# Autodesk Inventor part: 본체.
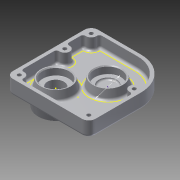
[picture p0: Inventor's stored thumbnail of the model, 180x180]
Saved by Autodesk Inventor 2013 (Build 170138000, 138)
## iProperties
Created: 2015-11
Part Number: 본체.
Material: 알루미늄 6061
Document SubType Name: Modeling
Designer: Administrator
Density: 1 g/cm^3
Author: Administrator
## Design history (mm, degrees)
sketch "스케치1"
  geometry: L1 (-44.906, -34.091)-(39.094, -34.091); L2 (47.094, -26.091)-(47.094, 28.909); L3 (7.094, 68.909)-(-44.906, 68.909); L4 (-52.906, 60.909)-(-52.906, -26.091); A1 r 40 centre (7.094, 28.909) between (47.094, 28.909) and (7.094, 68.909); A2 r 8 centre (-44.906, 60.909) between (-44.906, 68.909) and (-52.906, 60.909); A3 r 8 centre (-44.906, -26.091) between (-52.906, -26.091) and (-44.906, -34.091); A4 r 8 centre (39.094, -26.091) between (39.094, -34.091) and (47.094, -26.091); 4 further points
  constraints: 8 end point, 8 point on circle, 8 tangent, 6 point on line, 4 centre point, 2 equal radius, 2 parallel, 1 horizontal, 1 perpendicular
  dimensions: "d0" = 103 distance of point (-52.906, 68.909) point (-52.906, -34.091); "d2" = 100 distance of point (-52.906, -34.091) point (47.094, -34.091); "d3" = 40 radius of A1; "d4" = 8 radius of A2
extrude "돌출1" new body sketch "스케치1" distance "d5" = 18; taper "d6" = 0 deg
sketch "스케치2"
  geometry: L1 (47.094, -26.091)-(47.094, 28.909) reference; L2 (7.094, 68.909)-(-44.906, 68.909) reference; L3 (-52.906, 60.909)-(-52.906, -26.091) reference; L4 (-44.906, -34.091)-(39.094, -34.091) reference; A1 r 40 centre (7.094, 28.909) between (47.094, 28.909) and (7.094, 68.909) reference; A2 r 8 centre (-44.906, 60.909) between (-44.906, 68.909) and (-52.906, 60.909) reference; A3 r 8 centre (-44.906, -26.091) between (-52.906, -26.091) and (-44.906, -34.091) reference; A4 r 8 centre (39.094, -26.091) between (39.094, -34.091) and (47.094, -26.091) reference; 1 further point
feature "쉘1" dims "d9" = 4
sketch "스케치3"
  geometry: L1 (88, 4)-(88, 59) reference; L2 (52, 95)-(0, 95) reference; L3 (-4, 91)-(-4, 4) reference; L4 (0, 0)-(84, 0) reference; L5 (84, -4)-(0, -4) reference; L6 (-8, 4)-(-8, 91) reference; L7 (0, 99)-(52, 99) reference; L8 (92, 59)-(92, 4) reference; L9 (0, 59)-(84, 59); C1 r 6 at (0, 91); C2 r 6 at (0, 4); C3 r 6 at (0, 59); C4 r 6 at (84, 59); C5 r 6 at (84, 4); A1 r 4 centre (0, 91) between (0, 95) and (-4, 91) reference; A2 r 4 centre (0, 4) between (-4, 4) and (0, 0) reference; A3 r 4 centre (84, 4) between (84, 0) and (88, 4) reference; A4 r 36 centre (52, 59) between (88, 59) and (52, 95) reference; A5 r 4 centre (0, 91) between (0, 95) and (-4, 91) reference; A6 r 4 centre (0, 4) between (-4, 4) and (0, 0) reference; A7 r 8 centre (84, 4) between (84, -4) and (92, 4) reference; A8 r 8 centre (0, 4) between (-8, 4) and (0, -4) reference; A9 r 8 centre (0, 91) between (0, 99) and (-8, 91) reference; A10 r 40 centre (52, 59) between (92, 59) and (52, 99) reference; 1 further point
  constraints: 5 centre point, 4 coincident, 2 end point, 1 perpendicular
  dimensions: "d10" = 12 diameter of C1; "d12" = 6 radius of C2; "d14" = 6 radius of C3; "d15" = 84 distance of L9.start L9.end; "d16" = 6 radius of C4; "d17" = 6 radius of C5
extrude "돌출2" join sketch "스케치3" distance "d18" = 14; taper "d19" = 0 deg
fillet "모깎기2" dims "d21" = 3
fillet "모깎기3" dims "d22" = 3
sketch "스케치4"
  geometry: L1 (0, 89)-(43.056, 89) reference; L2 (-9.944, 64.944)-(-9.944, 79.056) reference; L3 (-9.944, 9.944)-(-9.944, 47.056) reference; L4 (66.111, 0)-(0, 0) reference; L5 (76.056, 47.056)-(76.056, 9.944) reference; A1 r 33 centre (43.056, 56) between (74.806, 64.997) and (43.056, 89) reference; A2 r 9 centre (-8.944, 88) between (-9.944, 79.056) and (0, 89) reference; A3 r 9 centre (-8.944, 56) between (-9.944, 47.056) and (-9.944, 64.944) reference; A4 r 9 centre (-8.944, 1) between (0, 0) and (-9.944, 9.944) reference; A5 r 9 centre (75.056, 1) between (76.056, 9.944) and (66.111, 0) reference; A6 r 9 centre (75.056, 56) between (74.806, 64.997) and (76.056, 47.056) reference; 1 further point
sketch "스케치5"
  geometry: L1 (0, 89)-(43.056, 89) reference; L2 (-9.944, 64.944)-(-9.944, 79.056) reference; L3 (-9.944, 9.944)-(-9.944, 47.056) reference; L4 (66.111, 0)-(0, 0) reference; L5 (76.056, 47.056)-(76.056, 9.944) reference; A1 r 33 centre (43.056, 56) between (74.806, 64.997) and (43.056, 89) reference; A2 r 9 centre (-8.944, 88) between (-9.944, 79.056) and (0, 89) reference; A3 r 9 centre (-8.944, 56) between (-9.944, 47.056) and (-9.944, 64.944) reference; A4 r 9 centre (-8.944, 1) between (0, 0) and (-9.944, 9.944) reference; A5 r 9 centre (75.056, 1) between (76.056, 9.944) and (66.111, 0) reference; A6 r 9 centre (75.056, 56) between (74.806, 64.997) and (76.056, 47.056) reference; 1 further point
sketch "스케치6"
  geometry: A1 r 6 centre (-44.906, -26.091) between (-38.943, -26.758) and (-45.573, -20.128) reference; A2 r 6 centre (-44.906, 28.909) between (-45.573, 22.946) and (-45.573, 34.872) reference; A3 r 6 centre (39.094, 28.909) between (38.927, 34.906) and (39.761, 22.946) reference; A4 r 8 centre (-44.906, 60.909) between (-44.906, 68.909) and (-52.906, 60.909) reference; A5 r 8 centre (39.094, -26.091) between (39.094, -34.091) and (47.094, -26.091) reference; 1 further point
hole "구멍1" sketch "스케치6" at (-44.906, 60.909), (-44.906, 28.909), (39.094, 28.909), (39.094, -26.091), (-44.906, -26.091) diameter "d23" = 4.5; stored, may be unused: countersink angle "d27" = 90 deg, drill point angle "d29" = 118 deg; dims "d24" = 6, "d25" = 4, "d26" = 2, "d28" = 8
sketch "스케치7"
  geometry: C1 r 2.25 at (-39.094, -26.091) reference; C2 r 2.25 at (44.906, 28.909) reference; C3 r 2.25 at (44.906, 60.909) reference; C4 r 2.25 at (-39.094, 28.909) reference; C5 r 2.25 at (44.906, -26.091) reference; 1 further point
hole "구멍2" sketch "스케치7" at (-39.094, 28.909), (-39.094, -26.091), (44.906, -26.091), (44.906, 28.909), (44.906, 60.909) diameter "d30" = 4.5; stored, may be unused: countersink angle "d34" = 90 deg, drill point angle "d36" = 118 deg; dims "d31" = 6, "d32" = 8, "d33" = 4.4, "d35" = 17
sketch "스케치8"
  geometry: L1 (-16.944, 88)-(-16.944, 1) reference; L2 (-8.944, -7)-(75.056, -7) reference; L3 (-16.944, 1)-(-16.944, -7); L4 (-9.944, -7)-(-16.944, -7); L5 (-16.944, -7)-(13.056, -7); L6 (13.056, -7)-(13.056, 23); L7 (13.056, 23)-(-16.944, 23); L8 (-16.944, 23)-(-16.944, -7); L9 (-16.944, -7)-(43.056, -7); L10 (43.056, -7)-(43.056, 56); L11 (43.056, 56)-(-16.944, 56); L12 (-16.944, 56)-(-16.944, -7); C1 r 20 at (13.056, 23); C2 r 20 at (43.056, 56); 1 further point
  constraints: 20 end point, 4 parallel, 4 perpendicular, 2 centre point, 2 coincident, 2 horizontal
  dimensions: "d37" = 30 distance of L7.end L6.end; "d38" = 30 distance of L6.end L5.end; "d40" = 20 radius of C1; "d41" = 60 distance of L11.end L10.end; "d42" = 63 distance of L10.end L9.end; "d43" = 20 radius of C2
extrude "돌출3" join sketch "스케치8" distance "d44" = 11; taper "d45" = -10 deg
fillet "모깎기4" dims "d46" = 3
sketch "스케치10"
  geometry: C1 r 18.06 at (0, 0) reference; 1 further point
hole "구멍4" sketch "스케치10" at (0, 0) diameter "d54" = 20; stored, may be unused: countersink angle "d58" = 90 deg, drill point angle "d60" = 118 deg; dims "d55" = 6, "d56" = 32, "d57" = 9, "d59" = 50
chamfer "모따기1" distance "d61" = 1; stored, may be unused: second distance "d62" = 2, angle "d63" = 45 deg
fillet "모깎기5" dims "d64" = 0.3
sketch "스케치11"
  geometry: C1 r 10 at (22.906, -4.091) reference; C2 r 25 at (22.906, -2.936); 1 further point
  constraints: 1 centre point
  dimensions: "d65" = 25 radius of C2
extrude "돌출4" join sketch "스케치11" distance "d66" = 15; taper "d67" = -10 deg
sketch "스케치15"
  geometry: L1 (52.906, -26.091)-(52.906, 60.909) reference; L2 (44.906, 68.909)-(-7.094, 68.909) reference; 2 further points
  constraints: 1 other
  dimensions: "d91" = 40 distance from line of L1 point (12.906, 48.909); "d92" = 20 distance from line of point (12.906, 48.909) L2
feature "엠보싱1" sketch "스케치15" dims "d93" = 0.5, "d94" = 0
fillet "모깎기8" dims "d95" = 3
fillet "모깎기9" dims "d96" = 3
sketch "스케치16"
  geometry: C1 r 18.06 at (0, 0) reference; C2 r 16 at (0, 0); 1 further point
  constraints: 1 centre point, 1 coincident
  dimensions: "d97" = 32 diameter of C2
extrude "돌출7" cut sketch "스케치16" distance "d98" = 9; taper "d99" = 0 deg
chamfer "모따기3" distance "d103" = 1; stored, may be unused: second distance "d104" = 2, angle "d105" = 45 deg
fillet "모깎기10" dims "d106" = 0.3
sketch "스케치18"
  geometry: C1 r 12.645 at (0, -1.155) reference; C2 r 14 at (0, -1.155); 1 further point
  constraints: 1 centre point, 1 coincident
  dimensions: "d107" = 28 diameter of C2
extrude "돌출9" cut sketch "스케치18" distance "d108" = 11; taper "d109" = 0 deg
chamfer "모따기4" distance "d110" = 1; stored, may be unused: second distance "d111" = 2, angle "d112" = 45 deg
fillet "모깎기11" dims "d113" = 0.3
sketch "스케치19"
  geometry: C1 r 13.7 at (0, 0) reference; C2 r 12 at (0, 0); 1 further point
  constraints: 1 centre point, 1 coincident
  dimensions: "d114" = 24 diameter of C2
extrude "돌출10" cut sketch "스케치19" distance "d115" = 2; taper "d116" = 0 deg
fillet "모깎기12" dims "d117" = 2
sketch "스케치20"
  geometry: C1 r 10 at (0, 0) reference; C2 r 10 at (0, 0); 1 further point
  constraints: 1 centre point, 1 coincident
  dimensions: "d118" = 20 diameter of C2
extrude "돌출11" cut sketch "스케치20" stored distance "d119" = 2; taper "d120" = 0 deg
node "작업 평면2"
  node "작업 평면1"
sketch "스케치21"
  geometry: 1 further point
node "작업 평면4"
  node "작업 평면3"
sketch "스케치22"
  geometry: L1 (-39.483, 1)-(1, 1) reference; L2 (4, 4)-(4, 15) reference; L3 (4, 15)-(8, 15) reference; L4 (8, 15)-(8, 0) reference; L5 (5, -3)-(-34.507, -3) reference; L6 (-39.675, -18)-(-47, -18) reference; L7 (-47, -18)-(-48, -17) reference; L8 (-48, -17)-(-48, -7.3) reference; L9 (-48.3, -7)-(-50, -7) reference; L10 (-50, -7)-(-50, -6.969) reference; L11 (-51.647, -5)-(-52, -3) reference; L12 (-52, -3)-(-52, 3) reference; L13 (-52, 3)-(-46.3, 3) reference; L14 (-46, 3.3)-(-46, 11) reference; L15 (-46, 11)-(-45, 12) reference; L16 (-45, 12)-(-43.94, 12) reference; L17 (-43.94, 12)-(-42.437, 3.479) reference; L18 (-81.563, 3.479)-(-80.06, 12) reference; L19 (-80.06, 12)-(-79, 12) reference; L20 (-79, 12)-(-78, 11) reference; L21 (-78, 11)-(-78, 3.3) reference; L22 (-77.7, 3)-(-72, 3) reference; L23 (-72, 3)-(-72, -3) reference; L24 (-72, -3)-(-72.353, -5) reference; L25 (-74, -6.969)-(-74, -7) reference; L26 (-74, -7)-(-75.7, -7) reference; L27 (-76, -7.3)-(-76, -17) reference; L28 (-76, -17)-(-77, -18) reference; L29 (-77, -18)-(-84.325, -18) reference; L30 (-92, 0)-(-92, 15) reference; L31 (-92, 15)-(-88, 15) reference; L32 (-88, 15)-(-88, 4) reference; L33 (-85, 1)-(-84.517, 1) reference; L34 (-52, -3)-(-52, -5); L35 (-52, -5)-(-50.588, -5); L36 (-50.588, -5)-(-52, -3); L37 (-39.483, 1)-(1, 1) reference; L38 (4, 4)-(4, 15) reference; L39 (4, 15)-(8, 15) reference; L40 (8, 15)-(8, 0) reference; L41 (5, -3)-(-34.507, -3) reference; L42 (-84.325, -18)-(-47, -18) reference; L43 (-47, -18)-(-48, -17) reference; L44 (-48, -17)-(-48, -7.3) reference; L45 (-48.3, -7)-(-50, -7) reference; L46 (-50, -7)-(-50, -6.969) reference; L47 (-51.647, -5)-(-52, -3) reference; L48 (-52, -3)-(-52, 3) reference; L49 (-52, 3)-(-46.3, 3) reference; L50 (-46, 3.3)-(-46, 11) reference; L51 (-46, 11)-(-45, 12) reference; L52 (-45, 12)-(-43.94, 12) reference; L53 (-43.94, 12)-(-42.437, 3.479) reference; L54 (-81.563, 3.479)-(-80.06, 12) reference; L55 (-80.06, 12)-(-79, 12) reference; L56 (-79, 12)-(-78, 11) reference; L57 (-78, 11)-(-78, 3.3) reference; L58 (-77.7, 3)-(-72, 3) reference; L59 (-72, 3)-(-72, -3) reference; L60 (-72, -3)-(-72.353, -5) reference; L61 (-74, -6.969)-(-74, -7) reference; L62 (-74, -7)-(-75.7, -7) reference; L63 (-76, -7.3)-(-76, -17) reference; L64 (-76, -17)-(-77, -18) reference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; A1 r 3 centre (1, 4) between (1, 1) and (4, 4) reference; A2 r 3 centre (5, 0) between (5, -3) and (8, 0) reference; A3 r 0.3 centre (-48.3, -7.3) between (-48, -7.3) and (-48.3, -7) reference; A4 r 2 centre (-52, -6.969) between (-50, -6.969) and (-51.647, -5) reference; A5 r 0.3 centre (-46.3, 3.3) between (-46.3, 3) and (-46, 3.3) reference; A6 r 3 centre (-39.483, 4) between (-42.437, 3.479) and (-39.483, 1) reference; A7 r 3 centre (-84.517, 4) between (-84.517, 1) and (-81.563, 3.479) reference; A8 r 0.3 centre (-77.7, 3.3) between (-78, 3.3) and (-77.7, 3) reference; A9 r 2 centre (-72, -6.969) between (-72.353, -5) and (-74, -6.969) reference; A10 r 0.3 centre (-75.7, -7.3) between (-75.7, -7) and (-76, -7.3) reference; A11 r 3 centre (-89, 0) between (-92, 0) and (-89.248, -2.99) reference; A12 r 3 centre (-85, 4) between (-88, 4) and (-85, 1) reference; A13 r 3 centre (1, 4) between (1, 1) and (4, 4) reference; A14 r 3 centre (5, 0) between (5, -3) and (8, 0) reference; A15 r 0.3 centre (-48.3, -7.3) between (-48, -7.3) and (-48.3, -7) reference; A16 r 2 centre (-52, -6.969) between (-50, -6.969) and (-51.647, -5) reference; A17 r 0.3 centre (-46.3, 3.3) between (-46.3, 3) and (-46, 3.3) reference; A18 r 3 centre (-39.483, 4) between (-42.437, 3.479) and (-39.483, 1) reference; A19 r 3 centre (-84.517, 4) between (-84.517, 1) and (-81.563, 3.479) reference; A20 r 0.3 centre (-77.7, 3.3) between (-78, 3.3) and (-77.7, 3) reference; A21 r 2 centre (-72, -6.969) between (-72.353, -5) and (-74, -6.969) reference; A22 r 0.3 centre (-75.7, -7.3) between (-75.7, -7) and (-76, -7.3) reference; A23 r 3 centre (-89, 0) between (-92, 0) and (-89.248, -2.99) reference; A24 r 3 centre (-85, 4) between (-88, 4) and (-85, 1) reference; 3 further points
  constraints: 8 end point, 3 perpendicular, 1 midpoint, 8 other
revolve "회전1" sketch "스케치22" stored, may be unused: angle "d123" = 90 deg
sketch "스케치23"
  geometry: 1 further point
sketch "스케치24" dims "d124" = 36
  geometry: C1 r 15 at (0, -1.155) reference; 3 further points
  constraints: 1 coincident, 1 vertical alignment, 2 other
hole "구멍6" sketch "스케치24" at (0, 16.845) diameter "d125" = 2.459; stored, may be unused: countersink angle "d129" = 90 deg, drill point angle "d131" = 118 deg; dims "d126" = 8, "d127" = 4, "d128" = 2, "d130" = 10
node "작업 평면6"
  node "작업 평면5"
sketch "스케치25"
  geometry: 1 further point
sketch "스케치26"
  geometry: L1 (0, 0)-(43.056, 0) reference; L2 (-9.944, -24.056)-(-9.944, -9.944) reference; L3 (-9.944, -79.056)-(-9.944, -41.944) reference; C1 r 20 at (43.056, -33); A1 r 9 centre (75.056, -33) between (74.806, -24.003) and (76.056, -41.944) reference; A2 r 33 centre (43.056, -33) between (74.806, -24.003) and (43.056, 0) reference; A3 r 9 centre (-8.944, -1) between (-9.944, -9.944) and (0, 0) reference; A4 r 9 centre (-8.944, -33) between (-9.944, -41.944) and (-9.944, -24.056) reference; A5 r 9 centre (-8.944, -88) between (-4.389, -80.238) and (-9.944, -79.056) reference; A6 r 22.517 centre (13.056, -66) between (25.742, -47.396) and (-4.389, -80.238) reference; 4 further points
  constraints: 1 centre point, 1 coincident, 1 other
  dimensions: "d136" = 40 diameter of C1
sketch "스케치27"
  geometry: C1 r 10 at (-7.094, 28.909) reference; C2 r 10 at (-7.094, 28.909); 1 further point
  constraints: 1 centre point, 1 coincident, 1 concentric
extrude "돌출12" join sketch "스케치27" distance "d137" = 4; taper "d138" = 0 deg
sketch "스케치28"
  geometry: C1 r 10 at (0, 0) reference; C2 r 15.7 at (0, 0) reference; C3 r 11 at (0, 0); 1 further point
  constraints: 1 centre point, 1 coincident
  dimensions: "d139" = 22 diameter of C3
extrude "돌출13" cut sketch "스케치28" distance "d140" = 2; taper "d141" = 0 deg
fillet "모깎기13" dims "d142" = 2
node "솔리드1"
pattern_circular "원형 패턴2" dims angle "d133" = 360 deg
node "절단 모서리 투영1"
node "절단 모서리 투영2"
node "절단 모서리 투영3"
other parameters: "d121" = -29.75
